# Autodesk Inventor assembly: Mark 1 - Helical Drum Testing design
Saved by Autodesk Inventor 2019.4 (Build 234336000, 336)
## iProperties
Created: 2020-06
Part Number: Mark 1 - Helical Drum Testing design
Document SubType Name: Assembly
Designer: Administrator
Title: Mark 1 - Helical Drum Testing design v8
Author: Administrator
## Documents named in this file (2)
- c:\worker\convert-fusion-r04\tmp\job-1\361\output\files\ac4d47d1-1bb6-4da9-8c39-f43feb3a69a4\f60798cc-0143-475c-818a-5e5342cf3ce1.iam
- c:\worker\convert-fusion-r04\tmp\job-1\361\output\files\ac4d47d1-1bb6-4da9-8c39-f43feb3a69a4\Mark 1 - Helical Drum Testing design v8.ipt
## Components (1 placed, 1 different names)
1. Mark 1 - Helical Drum Testing design v8
